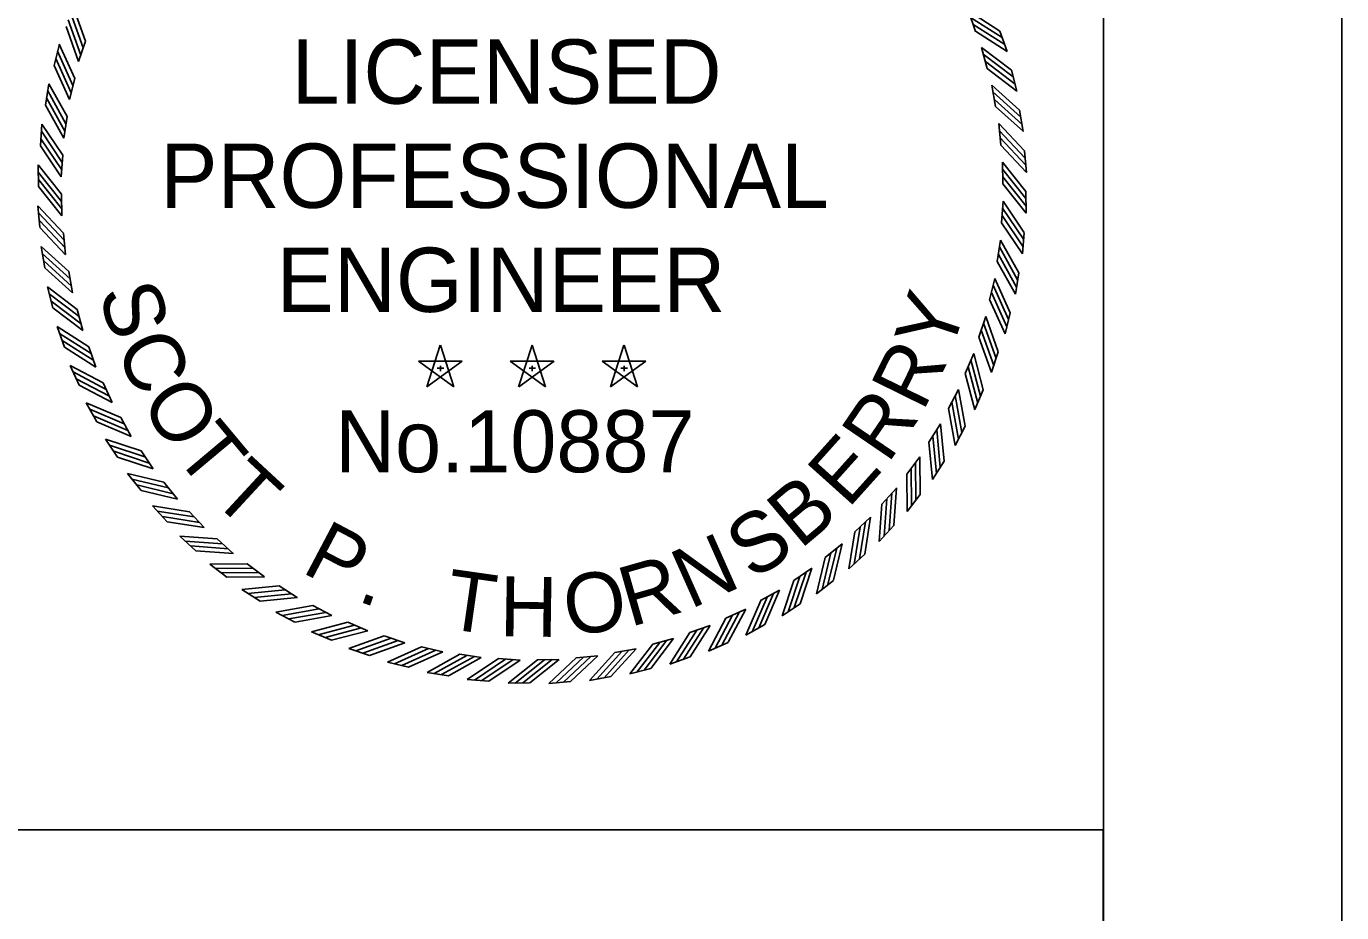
# Model space of a CAD drawing. Extents: x 0 to 1228740, y 0 to 152440.
# Drawn here: x 30.816 to 34, y 17.205 to 19.35 of the extents above; entities that cross this region are included whole.
import ezdxf

# ---------------------------------------------------------------- set-up
doc = ezdxf.new("R2010")
doc.units = 0
for name, color, linetype in [('R_Border', 7, 'Continuous'), ('R_No Plot', 7, 'Continuous'), ('STAMP_PP', 7, 'Continuous')]:
    doc.layers.add(name, color=color, linetype=linetype)

msp = doc.modelspace()

# ---------------------------------------------------------------- linework, layer by layer
at = {"layer": 'R_Border'}
msp.add_line((33.4231, 0.5768), (33.4231, 21.4232), dxfattribs=at)
msp.add_lwpolyline([(33.9999, 22), (0, 22), (0, 0), (33.9999, 0)], close=True, dxfattribs=at)
at = {"layer": 'R_No Plot'}
msp.add_lwpolyline([(27.1591, 21.4232), (1.516, 21.4232), (1.5167, 0.5746), (33.4224, 0.579), (33.4222, 17.4056), (30.6665, 17.4052), (30.6665, 19.4418), (30.6665, 20.1469), (30.6665, 20.4352), (27.1591, 20.4352)], close=True, dxfattribs=at)
at = {"layer": 'STAMP_PP'}
for p, q in [((33.0963, 19.3871), (33.1138, 19.3376)), ((33.1727, 19.3383), (33.1901, 19.2889)), ((30.8833, 19.2553), (30.8957, 19.3062)), ((30.9422, 19.2644), (30.9588, 19.3142)), ((33.1283, 19.2985), (33.1416, 19.2477)), ((33.2004, 19.2435), (33.2137, 19.1928)), ((30.8625, 19.1587), (30.8706, 19.2105)), ((30.9205, 19.1726), (30.9329, 19.2237)), ((33.1528, 19.2074), (33.1619, 19.1557)), ((33.2201, 19.1467), (33.2292, 19.0951)), ((30.8498, 19.0608), (30.8536, 19.113)), ((30.9065, 19.0794), (30.9146, 19.1313)), ((33.1698, 19.1147), (33.1746, 19.0624)), ((33.2319, 19.0486), (33.2367, 18.9964)), ((30.8452, 18.9621), (30.8447, 19.0145)), ((30.9001, 18.9854), (30.904, 19.0377)), ((33.179, 19.0209), (33.1795, 18.9684)), ((33.2354, 18.9499), (33.2359, 18.8975)), ((30.8488, 18.8634), (30.844, 18.9156)), ((30.9016, 18.8911), (30.9011, 18.9436)), ((33.1805, 18.9266), (33.1766, 18.8743)), ((33.2309, 18.8512), (33.227, 18.799)), ((30.9109, 18.7973), (30.906, 18.8496)), ((33.1742, 18.8326), (33.166, 18.7807)), ((30.8605, 18.7653), (30.8514, 18.8169)), ((30.9278, 18.7046), (30.9187, 18.7563)), ((33.1601, 18.7394), (33.1477, 18.6883)), ((33.2181, 18.7533), (33.21, 18.7015)), ((30.8803, 18.6685), (30.8669, 18.7192)), ((30.9524, 18.6136), (30.939, 18.6644)), ((33.1384, 18.6476), (33.1218, 18.5978)), ((33.1974, 18.6567), (33.185, 18.6058)), ((30.908, 18.5737), (30.8905, 18.6231)), ((30.9844, 18.5249), (30.9669, 18.5744)), ((31.8179, 18.578), (31.7852, 18.4774)), ((31.8506, 18.4774), (31.818, 18.5781)), ((32.0402, 18.578), (32.0074, 18.4774)), ((32.0729, 18.4774), (32.0403, 18.5781)), ((32.2625, 18.578), (32.2297, 18.4774)), ((32.2952, 18.4774), (32.2626, 18.5781)), ((31.8708, 18.5396), (31.765, 18.5397)), ((31.7651, 18.5396), (31.8506, 18.4773)), ((31.7853, 18.4774), (31.8709, 18.5395)), ((32.0931, 18.5396), (31.9873, 18.5397)), ((31.9874, 18.5396), (32.0729, 18.4773)), ((32.0076, 18.4774), (32.0932, 18.5395)), ((32.3153, 18.5396), (32.2096, 18.5397)), ((32.2096, 18.5396), (32.2952, 18.4773)), ((32.2298, 18.4774), (32.3155, 18.5395)), ((33.1092, 18.558), (33.0885, 18.5097)), ((33.1687, 18.5622), (33.1522, 18.5125)), ((30.9434, 18.4815), (30.9219, 18.5293)), ((31.8104, 18.5227), (31.8261, 18.5227)), ((31.818, 18.5283), (31.818, 18.515)), ((32.0327, 18.5227), (32.0484, 18.5227)), ((32.0403, 18.5283), (32.0403, 18.515)), ((32.255, 18.5227), (32.2707, 18.5227)), ((32.2626, 18.5283), (32.2626, 18.515)), ((31.0236, 18.4392), (31.002, 18.4871)), ((33.0727, 18.4711), (33.0481, 18.4247)), ((33.1323, 18.4703), (33.1117, 18.4222)), ((30.9863, 18.3926), (30.961, 18.4384)), ((31.0697, 18.357), (31.0443, 18.4029)), ((33.0291, 18.3875), (33.0008, 18.3433)), ((33.0885, 18.3818), (33.064, 18.3355)), ((31.0365, 18.3074), (31.0074, 18.351)), ((31.1225, 18.2789), (31.0934, 18.3226)), ((32.9788, 18.3078), (32.9469, 18.2661)), ((33.0375, 18.2972), (33.0092, 18.2531)), ((31.0934, 18.2268), (31.0609, 18.2678)), ((31.1816, 18.2054), (31.1489, 18.2465)), ((32.922, 18.2325), (32.8868, 18.1936)), ((32.9797, 18.2171), (32.9479, 18.1755)), ((31.1569, 18.1511), (31.1211, 18.1893)), ((31.2465, 18.137), (31.2106, 18.1753)), ((32.8593, 18.1622), (32.821, 18.1263)), ((32.9155, 18.1421), (32.8803, 18.1032)), ((31.2264, 18.0809), (31.1875, 18.116)), ((31.3168, 18.0743), (31.2779, 18.1095)), ((32.7909, 18.0973), (32.7498, 18.0646)), ((32.8453, 18.0726), (32.807, 18.0367)), ((31.3014, 18.0166), (31.2598, 18.0484)), ((31.3921, 18.0175), (31.3504, 18.0494)), ((32.7175, 18.0382), (32.6738, 18.0091)), ((31.4718, 17.9672), (31.4276, 17.9955)), ((32.7696, 18.0091), (32.7285, 17.9766)), ((31.3815, 17.9588), (31.3374, 17.9871)), ((32.6394, 17.9854), (32.5934, 17.96)), ((31.4661, 17.9078), (31.4198, 17.9323)), ((31.5554, 17.9237), (31.509, 17.9482)), ((32.5572, 17.9393), (32.5093, 17.9177)), ((32.6889, 17.9521), (32.6453, 17.9231)), ((31.6423, 17.8871), (31.594, 17.9078)), ((32.4714, 17.9001), (32.4219, 17.8826)), ((32.6038, 17.902), (32.5579, 17.8767)), ((31.5547, 17.864), (31.5065, 17.8846)), ((31.732, 17.8579), (31.6821, 17.8745)), ((32.3828, 17.8681), (32.332, 17.8547)), ((31.6465, 17.8276), (31.5968, 17.8442)), ((31.8237, 17.8362), (31.7727, 17.8486)), ((32.2918, 17.8435), (32.24, 17.8344)), ((32.5148, 17.8591), (32.467, 17.8376)), ((31.741, 17.7989), (31.6901, 17.8113)), ((31.9169, 17.8221), (31.865, 17.8303)), ((32.011, 17.8158), (31.9586, 17.8197)), ((32.1052, 17.8173), (32.0527, 17.8168)), ((32.199, 17.8265), (32.1467, 17.8217)), ((32.4226, 17.8237), (32.3732, 17.8062)), ((31.8376, 17.7782), (31.7858, 17.7863)), ((31.9355, 17.7655), (31.8833, 17.7693)), ((32.231, 17.7762), (32.1794, 17.7671)), ((32.3278, 17.796), (32.2771, 17.7826)), ((32.0342, 17.7609), (31.9818, 17.7604)), ((32.1329, 17.7645), (32.0808, 17.7596))]:
    msp.add_line(p, q, dxfattribs=at)
for points in [[(30.9588, 19.3142), (30.9285, 19.3996)], [(30.9477, 19.2802), (30.9174, 19.3657)], [(30.9531, 19.2976), (30.9228, 19.3831)], [(33.0962, 19.3872), (33.1726, 19.3384)], [(33.1017, 19.3712), (33.1781, 19.3224)], [(30.9423, 19.2643), (30.9119, 19.3497)], [(33.1081, 19.3542), (33.1845, 19.3054)], [(33.1138, 19.3377), (33.1902, 19.2889)], [(30.9329, 19.2236), (30.8956, 19.3063)], [(33.1282, 19.2985), (33.2003, 19.2435)], [(30.9247, 19.1889), (30.8874, 19.2716)], [(30.9286, 19.2067), (30.8913, 19.2894)], [(33.1323, 19.2822), (33.2044, 19.2272)], [(33.1373, 19.2646), (33.2095, 19.2097)], [(30.9206, 19.1726), (30.8833, 19.2552)], [(33.1416, 19.2477), (33.2138, 19.1928)], [(30.9146, 19.1313), (30.8706, 19.2106)], [(33.1528, 19.2075), (33.2201, 19.1468)], [(30.9093, 19.096), (30.8653, 19.1753)], [(30.9117, 19.114), (30.8677, 19.1933)], [(33.1555, 19.1909), (33.2229, 19.1301)], [(33.1591, 19.173), (33.2264, 19.1123)], [(30.9065, 19.0794), (30.8625, 19.1587)], [(33.162, 19.1558), (33.2293, 19.0951)], [(30.904, 19.0377), (30.8536, 19.1131)], [(33.1697, 19.1148), (33.2318, 19.0487)], [(30.9016, 19.0021), (30.8512, 19.0775)], [(30.9025, 19.0203), (30.8521, 19.0957)], [(33.1711, 19.098), (33.2332, 19.0319)], [(33.1732, 19.0799), (33.2353, 19.0138)], [(30.9002, 18.9853), (30.8498, 19.0607)], [(33.1746, 19.0625), (33.2367, 18.9964)], [(30.9011, 18.9436), (30.8447, 19.0146)], [(33.179, 19.021), (33.2354, 18.95)], [(30.9011, 18.9261), (30.8447, 18.9971)], [(30.9017, 18.9079), (30.8452, 18.9789)], [(33.179, 19.0041), (33.2354, 18.9331)], [(33.1795, 18.9859), (33.236, 18.9149)], [(30.9017, 18.891), (30.8452, 18.962)], [(33.1795, 18.9684), (33.236, 18.8975)], [(30.906, 18.8495), (30.8439, 18.9156)], [(33.1805, 18.9267), (33.2308, 18.8513)], [(30.9074, 18.8321), (30.8454, 18.8982)], [(33.1781, 18.8917), (33.2285, 18.8163)], [(33.1791, 18.9099), (33.2294, 18.8345)], [(30.9095, 18.814), (30.8474, 18.8801)], [(30.9109, 18.7972), (30.8488, 18.8633)], [(33.1767, 18.8743), (33.227, 18.7989)], [(33.1741, 18.8327), (33.2181, 18.7534)], [(30.9187, 18.7562), (30.8513, 18.817)], [(30.9215, 18.739), (30.8542, 18.7997)], [(33.1689, 18.798), (33.2129, 18.7187)], [(33.1714, 18.816), (33.2153, 18.7367)], [(30.9251, 18.7212), (30.8578, 18.7819)], [(30.9279, 18.7045), (30.8605, 18.7652)], [(33.1661, 18.7808), (33.21, 18.7015)], [(33.1601, 18.7395), (33.1973, 18.6568)], [(30.939, 18.6643), (30.8669, 18.7192)], [(30.9433, 18.6474), (30.8712, 18.7023)], [(33.152, 18.7053), (33.1893, 18.6227)], [(33.1559, 18.7231), (33.1932, 18.6404)], [(30.9483, 18.6299), (30.8762, 18.6848)], [(30.9524, 18.6135), (30.8803, 18.6685)], [(33.1477, 18.6884), (33.185, 18.6057)], [(33.1329, 18.6318), (33.1632, 18.5463)], [(33.1384, 18.6477), (33.1687, 18.5623)], [(30.9669, 18.5743), (30.8904, 18.6232)], [(30.9725, 18.5578), (30.8961, 18.6066)], [(33.1219, 18.5979), (33.1522, 18.5124)], [(33.1275, 18.6144), (33.1578, 18.5289)], [(30.979, 18.5408), (30.9026, 18.5896)], [(30.9844, 18.5248), (30.908, 18.5737)], [(33.1024, 18.5427), (33.1255, 18.455)], [(33.1092, 18.5581), (33.1323, 18.4704)], [(31.002, 18.487), (30.9219, 18.5293)], [(31.009, 18.471), (30.9289, 18.5133)], [(33.0886, 18.5098), (33.1117, 18.4221)], [(33.0956, 18.5258), (33.1188, 18.4381)], [(31.0169, 18.4546), (30.9367, 18.4969)], [(31.0237, 18.4391), (30.9435, 18.4815)], [(33.0727, 18.4712), (33.0885, 18.3819)], [(31.0443, 18.4029), (30.9609, 18.4384)], [(33.0565, 18.4401), (33.0723, 18.3508)], [(33.0646, 18.4564), (33.0805, 18.3671)], [(31.0526, 18.3875), (30.9692, 18.4231)], [(31.0618, 18.3718), (30.9784, 18.4073)], [(33.0482, 18.4247), (33.064, 18.3355)], [(31.0698, 18.3569), (30.9864, 18.3925)], [(33.0199, 18.3735), (33.0283, 18.2832)], [(33.0291, 18.3876), (33.0375, 18.2973)], [(31.0934, 18.3225), (31.0073, 18.3511)], [(33.0008, 18.3433), (33.0093, 18.253)], [(33.0104, 18.3579), (33.0188, 18.2677)], [(31.1029, 18.3079), (31.0169, 18.3364)], [(31.1134, 18.293), (31.0273, 18.3215)], [(31.1226, 18.2788), (31.0365, 18.3074)], [(32.9577, 18.2799), (32.9586, 18.1892)], [(32.9684, 18.2946), (32.9693, 18.2039)], [(32.9788, 18.3079), (32.9797, 18.2172)], [(31.1489, 18.2465), (31.0608, 18.2678)], [(31.1597, 18.2327), (31.0715, 18.254)], [(32.947, 18.2661), (32.9479, 18.1754)], [(31.1713, 18.2187), (31.0832, 18.24)], [(31.1817, 18.2054), (31.0935, 18.2267)], [(32.9106, 18.2202), (32.9041, 18.1298)], [(32.9221, 18.2326), (32.9155, 18.1422)], [(31.2106, 18.1753), (31.121, 18.1893)], [(32.8869, 18.1936), (32.8803, 18.1031)], [(32.8987, 18.2064), (32.8922, 18.116)], [(31.2224, 18.1624), (31.1328, 18.1764)], [(31.2351, 18.1494), (31.1456, 18.1634)], [(31.2466, 18.137), (31.157, 18.151)], [(32.8469, 18.1508), (32.8329, 18.0613)], [(32.8593, 18.1623), (32.8453, 18.0727)], [(32.821, 18.1263), (32.807, 18.0367)], [(32.8339, 18.1381), (32.8199, 18.0485)], [(31.2779, 18.1094), (31.1875, 18.116)], [(31.2907, 18.0976), (31.2003, 18.1042)], [(31.3045, 18.0857), (31.2141, 18.0923)], [(32.7776, 18.087), (32.7563, 17.9989)], [(32.791, 18.0973), (32.7696, 18.0092)], [(31.3169, 18.0743), (31.2265, 18.0808)], [(32.7499, 18.0646), (32.7285, 17.9765)], [(32.7636, 18.0754), (32.7423, 17.9872)], [(31.3504, 18.0494), (31.2597, 18.0484)], [(31.3642, 18.0386), (31.2735, 18.0377)], [(31.3789, 18.0279), (31.2882, 18.027)], [(32.7034, 18.0291), (32.6748, 17.943)], [(32.7175, 18.0383), (32.6889, 17.9522)], [(31.3922, 18.0175), (31.3015, 18.0166)], [(31.4276, 17.9955), (31.3373, 17.9871)], [(32.6738, 18.0091), (32.6453, 17.923)], [(32.6884, 18.0186), (32.6599, 17.9326)], [(31.4422, 17.9859), (31.352, 17.9775)], [(31.4578, 17.9765), (31.3675, 17.968)], [(31.4719, 17.9672), (31.3816, 17.9588)], [(32.5935, 17.96), (32.5579, 17.8766)], [(32.6088, 17.9683), (32.5732, 17.8849)], [(32.6246, 17.9775), (32.589, 17.8941)], [(32.6394, 17.9855), (32.6038, 17.9021)], [(31.509, 17.9482), (31.4198, 17.9323)], [(31.5244, 17.9399), (31.4351, 17.924)], [(31.5407, 17.9317), (31.4514, 17.9159)], [(32.5418, 17.9326), (32.4994, 17.8524)], [(32.5572, 17.9393), (32.5149, 17.8592)], [(31.5555, 17.9237), (31.4662, 17.9078)], [(31.5941, 17.9077), (31.5064, 17.8846)], [(31.6101, 17.9007), (31.5224, 17.8776)], [(32.4715, 17.9001), (32.4227, 17.8237)], [(32.5093, 17.9177), (32.467, 17.8375)], [(32.5253, 17.9247), (32.483, 17.8446)], [(31.627, 17.8939), (31.5393, 17.8708)], [(31.6424, 17.8872), (31.5547, 17.864)], [(31.6822, 17.8745), (31.5967, 17.8442)], [(31.6987, 17.8688), (31.6132, 17.8385)], [(31.7161, 17.8634), (31.6306, 17.8331)], [(32.3665, 17.864), (32.3115, 17.7919)], [(32.3828, 17.8681), (32.3279, 17.796)], [(32.422, 17.8825), (32.3732, 17.8061)], [(32.4385, 17.8882), (32.3897, 17.8118)], [(32.4555, 17.8947), (32.4067, 17.8182)], [(31.732, 17.8579), (31.6466, 17.8276)], [(31.7727, 17.8486), (31.69, 17.8113)], [(31.7896, 17.8443), (31.707, 17.807)], [(31.8074, 17.8404), (31.7248, 17.8031)], [(31.8238, 17.8362), (31.7411, 17.799)], [(32.2401, 17.8344), (32.1794, 17.767)], [(32.2573, 17.8372), (32.1966, 17.7699)], [(32.2752, 17.8408), (32.2144, 17.7735)], [(32.2918, 17.8436), (32.2311, 17.7762)], [(32.332, 17.8547), (32.2771, 17.7826)], [(32.349, 17.859), (32.294, 17.7869)], [(31.8651, 17.8303), (31.7858, 17.7863)], [(31.8823, 17.8274), (31.803, 17.7834)], [(31.9003, 17.825), (31.821, 17.781)], [(31.917, 17.8222), (31.8377, 17.7782)], [(31.9586, 17.8196), (31.8832, 17.7693)], [(31.976, 17.8182), (31.9006, 17.7678)], [(31.9942, 17.8173), (31.9188, 17.7669)], [(32.011, 17.8159), (31.9356, 17.7655)], [(32.0528, 17.8168), (31.9818, 17.7604)], [(32.0702, 17.8168), (31.9992, 17.7604)], [(32.0884, 17.8173), (32.0174, 17.7609)], [(32.1053, 17.8173), (32.0343, 17.7609)], [(32.1468, 17.8217), (32.0807, 17.7596)], [(32.1642, 17.8231), (32.0981, 17.761)], [(32.1823, 17.8252), (32.1162, 17.7631)], [(32.1991, 17.8266), (32.133, 17.7645)]]:
    msp.add_lwpolyline(points, dxfattribs=at)

# ---------------------------------------------------------------- texts
for s, height, p in [('LICENSED', 0.15559, (31.4583, 19.1624)), ('PROFESSIONAL', 0.155591, (31.1397, 18.9105)), ('ENGINEER', 0.15559, (31.4213, 18.6586)), ('No.10887', 0.15003, (31.5635, 18.2706))]:
    msp.add_text(s, height=height, dxfattribs=at).set_placement(p)
for s, rotation, p in [('S', 286.9475, (30.9894, 18.7062)), ('Y', 71.7733, (33.0524, 18.5517)), ('C', 294.2435, (31.0297, 18.5741)), ('R', 63.7477, (32.9861, 18.415)), ('O', 301.9044, (31.0897, 18.4421)), ('R', 55.7221, (32.9014, 18.289)), ('T', 309.93, (31.1708, 18.3137)), ('E', 48.0613, (32.8048, 18.1808)), ('T', 317.226, (31.2594, 18.2078)), ('B', 40.0357, (32.6892, 18.0824)), ('P', 332.1828, (31.4791, 18.0303)), ('S', 32.7397, (32.5731, 18.0077)), ('N', 23.9845, (32.4226, 17.9384)), ('R', 15.9589, (32.2768, 17.8957)), ('T', 351.882, (31.8242, 17.8936)), ('O', 7.9332, (32.1266, 17.8738)), ('H', 359.178, (31.9609, 17.8741)), ('.', 340.2084, (31.6139, 17.9603))]:
    msp.add_text(s, height=0.1448, rotation=rotation, dxfattribs=at).set_placement(p)

doc.saveas('drawing.dxf')
